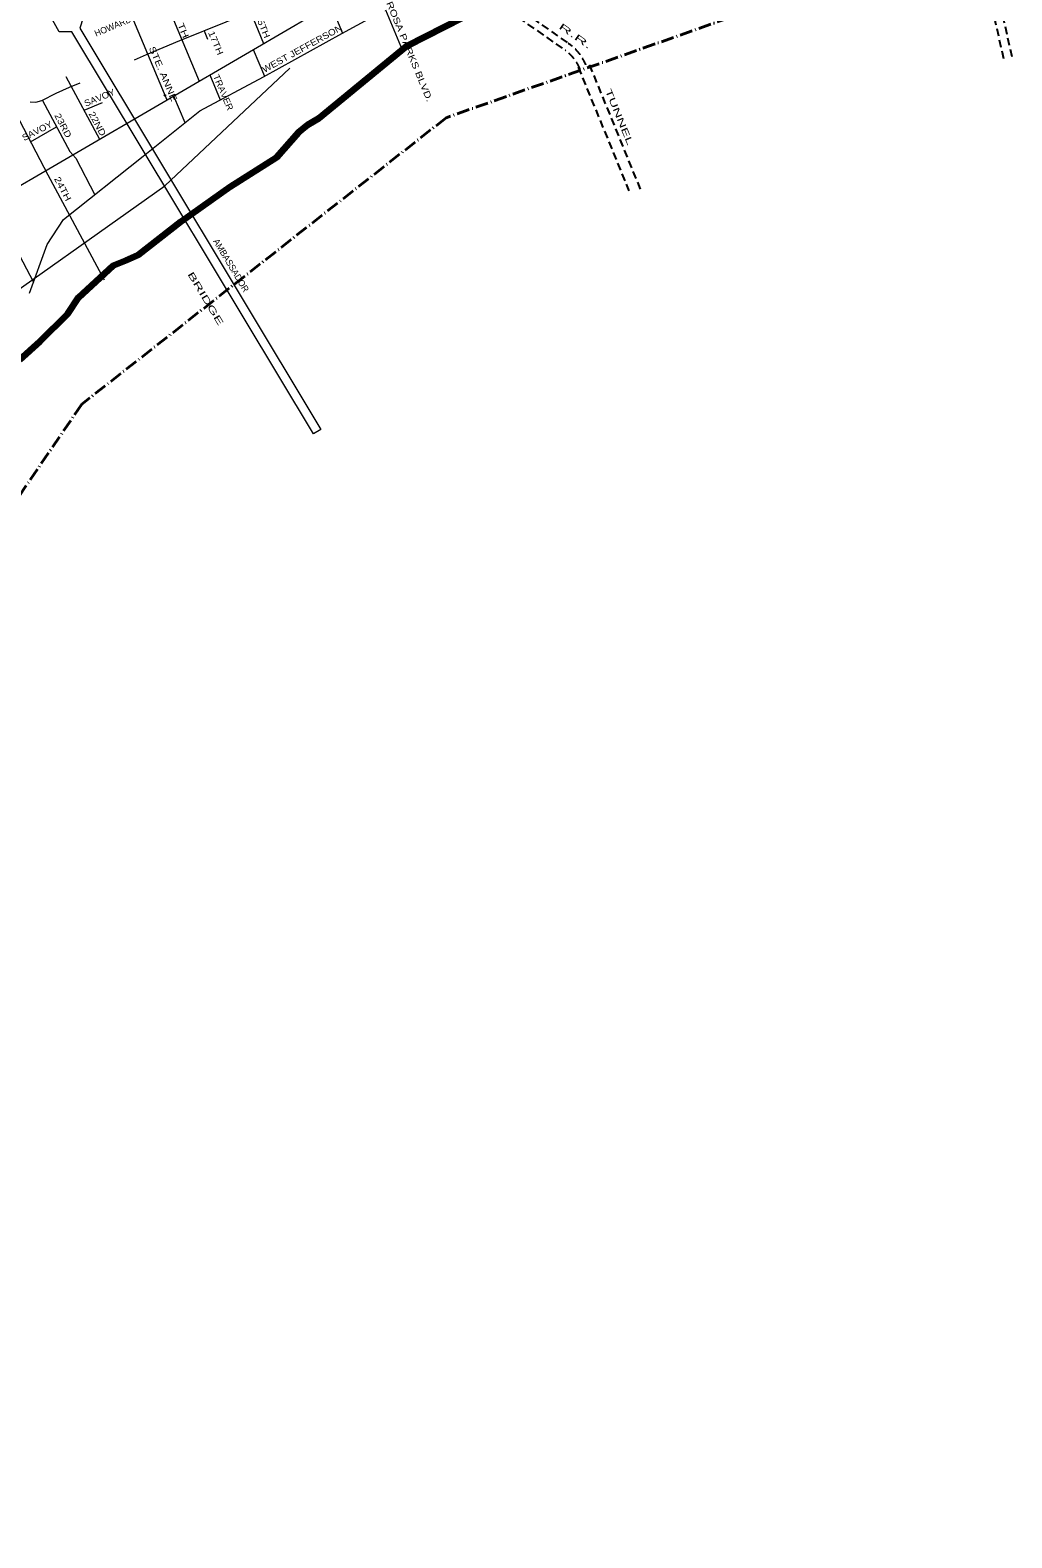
# Model space of a CAD drawing. Extents: x 34705 to 138605, y 34275 to 143551.
# Drawn here: x 90524 to 102032, y 78375 to 96052 of the extents above; entities that cross this region are included whole.
import ezdxf
from ezdxf.enums import TextEntityAlignment as Align

# ---------------------------------------------------------------- set-up
doc = ezdxf.new("R2010")
doc.units = 0
doc.header["$LTSCALE"] = 30
doc.header["$PDMODE"] = 32
doc.header["$PDSIZE"] = 15
doc.linetypes.add('DOT_DASHED', pattern=[7.7, 5, -1.2, 0.3, -1.2])
doc.linetypes.add('MEDIUM_DASHED', pattern=[4.5, 3, -1.5])
for name, color, linetype, lineweight in [('1', 7, 'Continuous', 13), ('11', 7, 'Continuous', 13), ('50', 7, 'Continuous', 13), ('56', 7, 'DOT_DASHED', 40), ('58', 7, 'Continuous', 106), ('7', 7, 'MEDIUM_DASHED', 25)]:
    doc.layers.add(name, color=color, linetype=linetype, lineweight=lineweight)

msp = doc.modelspace()

# ---------------------------------------------------------------- linework, layer by layer
at = {"layer": '1'}
for p, q in [((90708, 98606.4), (92126.39, 95234.65)), ((91866.2, 96982.02), (92506.68, 95456.18)), ((94044.06, 96354.84), (94185.15, 96016.57)), ((93108.35, 96266.62), (93259.29, 95894.99)), ((94690.14, 96289.45), (94886.57, 95822.43)), ((92563.87, 96045.83), (92604.58, 95948.58)), ((93138.44, 95824.18), (93270.68, 95512.92)), ((90942.88, 95507.96), (91338.19, 94775.5)), ((92630.31, 95528.2), (92751.16, 95235.83)), ((90987.34, 95383.21), (91111.42, 95434.77)), ((91156.19, 95112.73), (91372.88, 95202.33)), ((92205.15, 95280.53), (92338.1, 94968.27)), ((90528.98, 94741.33), (90834.24, 94917.5))]:
    msp.add_line(p, q, dxfattribs=at)
for points in [[(83944.94, 105858.26), (84407.41, 104899.6), (85247.05, 103134.47), (85273.29, 103095.09), (85312.65, 103009.79), (86306.44, 101019.92), (86450.76, 100875.56), (86857.46, 100075.01), (86896.82, 99851.91), (87605.27, 98513.29), (87644.63, 98395.18), (88458.03, 96846.58), (88523.63, 96780.96), (89683.06, 94633.6), (89886.41, 94266.14), (90011.05, 94036.48), (90103.12, 93970.1), (90563.88, 93097.88)], [(68439.64, 83130.91), (69240.62, 83379.94), (69351.18, 83443.98), (71166.8, 83996.99), (73724.39, 85148.13), (74227.76, 85392.62), (75135.57, 85904.88), (77195.6, 86958.51), (78743.53, 87721.08), (81322.94, 89059.96), (82067.81, 89449.98), (83313.14, 90160.16), (86113.68, 91749.34), (89963.15, 93974.49), (93143.39, 95827.08), (94534.21, 96642.05), (99929.58, 99752.11)], [(91747.97, 95706.14), (91889.33, 95767.41), (92279.23, 95930.4), (93363.13, 96369.94)], [(90515.98, 92967.43), (90725.47, 93537.9), (90915.08, 93830.44), (91848.6, 94574.07), (92512.17, 95108.44), (93259.78, 95506.92), (94179.23, 96013.36), (94673.87, 96281.14)], [(90661.46, 95226.04), (90830.22, 95313.36), (90987.34, 95383.21)], [(90524.49, 95211.49), (90589.35, 95208.36), (90661.83, 95226.44)], [(90668.24, 95228.42), (90988.44, 94628.69), (91060.6, 94549.95), (91281.01, 94121.94)], [(90397.52, 94992.28), (90731.41, 94354.89), (91391.74, 93123.57)]]:
    msp.add_lwpolyline(points, dxfattribs=at)
msp.add_point((92104.06, 95287.74), dxfattribs=at)
at = {"layer": '50'}
msp.add_lwpolyline([(75738.94, 84768.1), (76212.46, 85218.25), (76415.88, 85360.27), (77466.17, 85940.83), (78326.34, 86453.07), (78907.68, 86761.74), (80816.14, 87764.18), (82451.17, 88642.55), (85727.5, 90394.26), (87169.71, 91158.67), (87923.98, 91579.11), (89453.5, 92401.96), (89772.51, 92578.81), (92103.98, 94226.85), (93569.85, 95605.87)], dxfattribs=at)
at = {"layer": '56'}
msp.add_lwpolyline([(101333.7, 97121.46), (95399.61, 95024.99), (91130.54, 91667.28), (86478.26, 84854.43), (84052.84, 78374.69)], dxfattribs=at)
at = {"layer": '58'}
msp.add_lwpolyline([(96460.77, 96641.8), (94939.86, 95864.74), (93908.01, 95017.12), (93776.43, 94937.21), (93668.75, 94851.31), (93411.39, 94557.67), (92869.13, 94214.06), (92288.94, 93806.54), (91790.43, 93413), (91648.92, 93353.06), (91491.48, 93289.12), (91090.95, 92917.83), (90962.73, 92720.73), (90638.91, 92403.01), (90400.67, 92186.68)], dxfattribs=at)
at = {"layer": '7'}
for p, q in [((101299.07, 98576.96), (101933.91, 95712.27)), ((101396.7, 98598.6), (102031.54, 95733.9)), ((95860.98, 96580.19), (96831.69, 95897.79)), ((95803.68, 96512.38), (96777.2, 95828.01)), ((97078.57, 95645.59), (97676.91, 94186.23)), ((96948.64, 95618.72), (97543.78, 94167.15))]:
    msp.add_line(p, q, dxfattribs=at)
at = {"layer": '7', "linetype": 'Continuous', "lineweight": 13}
msp.add_lwpolyline([(90940.86, 96561), (91145.86, 96195.59), (91107.24, 96075.3), (93932.18, 91369.35), (93844.25, 91320.13), (91012.91, 96033.52), (90866.14, 96033.62), (90647.37, 96433.23)], close=True, dxfattribs=at)
at = {"layer": '7'}
for centre, radius, start, end in [((96507.68, 95407.44), 499.79, 22.53894, 54.76732), ((96519.24, 95431.68), 561.17, 22.27222, 56.17819)]:
    msp.add_arc(centre, radius, start, end, dxfattribs=at)

# ---------------------------------------------------------------- texts
at = {"layer": '11'}
for s, rotation, width, p in [('ROSA PARKS BLVD. ', 292.459, 1.3, (94944.39, 95770.88)), ('18 TH', 292.909, 1.35, (92247.65, 96120.8)), ('15TH', 292.234, 1.2, (93215.51, 96086.58)), ('17TH', 292.829, 1.2, (92666.05, 95887.64)), ('WEST JEFFERSON', 28.846, 1.15, (93730.67, 95803.82)), ('R.R.', 324.893, 2.2, (96892.86, 95953.02)), ('STE. ANNE', 293.046, 1.3, (92048.58, 95525.55)), ('TRAVER', 292.919, 1.1, (92753.26, 95307.7)), ('SAVOY', 22.465, 1.1, (91351.78, 95226.1)), ('TUNNEL', 292.294, 1.75, (97395.38, 95020.62)), ('SAVOY', 27.091, 1.1, (90622.8, 94837.66)), ('23RD', 297.708, 1.2, (90876.88, 94917.04)), ('22ND', 298.135, 1.2, (91279.09, 94937.57)), ('24TH', 297.712, 1.25, (90873.57, 94174.55)), ('BRIDGE', 300.984, 1.85, (92549.34, 92886.37))]:
    msp.add_text(s, height=75, rotation=rotation, dxfattribs=dict(at, width=width)).set_placement(p, align=Align.CENTER)
for s, rotation, p in [('HOWARD', 22.835, (91507.75, 96063.19)), ('AMBASSADOR', 300.984, (92847.91, 93274.82))]:
    msp.add_text(s, height=75, rotation=rotation, dxfattribs=at).set_placement(p, align=Align.CENTER)

doc.saveas('drawing.dxf')
